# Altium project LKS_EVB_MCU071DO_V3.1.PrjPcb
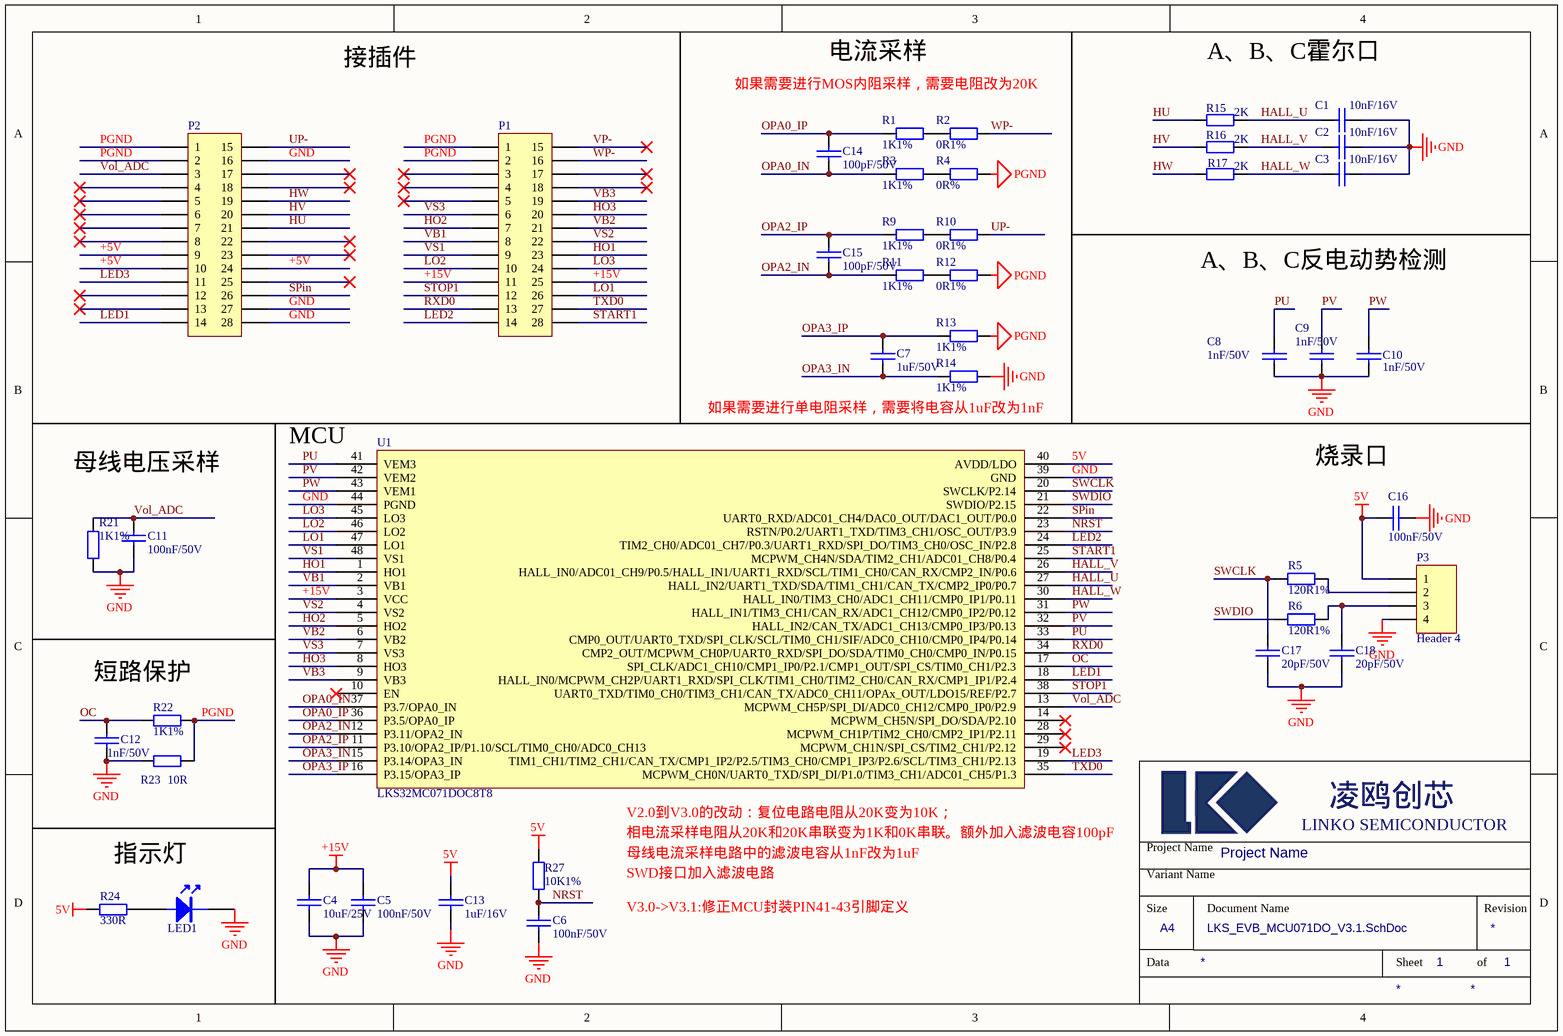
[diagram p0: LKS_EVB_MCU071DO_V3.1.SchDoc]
1 sheet, 43 parts. Net scope: global (net labels, ports and power ports of the same name join across sheets).
Board file: LKS_EVB_MCU071DO_V3.0.PcbDoc

## Sheet LKS_EVB_MCU071DO_V3.1.SchDoc
size A4; SheetNumber: 1; SheetTotal: 1; Variant Name: [No Variations]; Size: A3

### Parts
C1  10nF/16V  [0603C]
C2  10nF/16V  [0603C]
C3  10nF/16V  [0603C]
C4  10uF/25V  [0603C]
C5  100nF/50V  [0603C]
C6  100nF/50V  [0603C]
C7  1uF/50V  [0603C]
C8  1nF/50V  [0603C]
C9  1nF/50V  [0603C]
C10  1nF/50V  [0603C]
C11  100nF/50V  [0603C]
C12  1nF/50V  [0603C]
C13  1uF/16V  [0603C]
C14  100pF/50V  [0603C]
C15  100pF/50V  [0603C]
C16  100nF/50V  [0603C]
C17  20pF/50V  [0603C]
C18  20pF/50V  [0603C]
LED1  LED  [LED 0603R]  (value not drawn)
P1  Header 14X2A  [HDR 2X14 顶层]  (value not drawn)
P2  Header 14X2A  [HDR 2X14 顶层]  (value not drawn)
P3  Header 4  [HDR 1X4]
R1  1K1%  [0603R]
R2  0R1%  [0603R]
R3  1K1%  [0603R]
R4  0R%  [0603R]
R5  120R1%  [0603R]
R6  120R1%  [0603R]
R9  1K1%  [0603R]
R10  0R1%  [0603R]
R11  1K1%  [0603R]
R12  0R1%  [0603R]
R13  1K1%  [0603R]
R14  1K1%  [0603R]
R15  2K  [0603R]
R16  2K  [0603R]
R17  2K  [0603R]
R21  1K1%  [0603R]
R22  1K1%  [0603R]
R23  10R  [0603R]
R24  330R  [0603R]
R27  10K1%  [0603R]
U1  LKS32MC071DOC8T8  [TQFP48]

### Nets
5V: C13.2 C16.1 P3.1 R24.1 R27.2 U1.40(AVDD/LDO)
+15V: C4.2 C5.2 P1.11 P1.25 U1.3(VCC)
GND: C1.2 C2.2 C3.2 C4.1 C5.1 C6.2 C8.2 C9.2 C10.2 C11.1 C12.1 C13.1 C16.2 C17.1 C18.1 LED1.2(K) P2.16 P2.27 P2.28 P3.4 R14.1 R21.1 R23.2 U1.39(GND) U1.44(PGND)
PGND: P1.1 P1.2 P2.1 P2.2 R4.1 R12.1 R13.1 R22.2 R23.1
+5V: P2.9 P2.10 P2.24
HALL_U: C1.1 R15.2 U1.27(HALL_IN2/UART1_TXD/SDA/TIM1_CH1/CAN_TX/CMP2_IP0/P0.7)
HALL_V: C2.1 R16.2 U1.26(HALL_IN0/ADC01_CH9/P0.5/HALL_IN1/UART1_RXD/SCL/TIM1_CH0/CAN_RX/CMP2_IN/P0.6)
HALL_W: C3.1 R17.2 U1.30(HALL_IN0/TIM3_CH0/ADC1_CH11/CMP0_IP1/P0.11)
HO1: P1.23 U1.1(HO1)
HO2: P1.7 U1.5(HO2)
HO3: P1.20 U1.8(HO3)
HU: P2.21 R15.1
HV: P2.20 R16.1
HW: P2.19 R17.1
LED1: P2.14 U1.18(HALL_IN0/MCPWM_CH2P/UART1_RXD/SPI_CLK/TIM1_CH0/TIM2_CH0/CAN_RX/CMP1_IP1/P2.4)
LED2: P1.14 U1.24(TIM2_CH0/ADC01_CH7/P0.3/UART1_RXD/SPI_DO/TIM3_CH0/OSC_IN/P2.8)
LED3: P2.11 U1.19(TIM1_CH1/TIM2_CH1/CAN_TX/CMP1_IP2/P2.5/TIM3_CH0/CMP1_IP3/P2.6/SCL/TIM3_CH1/P2.13)
LO1: P1.26 U1.47(LO1)
LO2: P1.10 U1.46(LO2)
LO3: P1.24 U1.45(LO3)
NRST: C6.1 R27.1 U1.23(RSTN/P0.2/UART1_TXD/TIM3_CH1/OSC_OUT/P3.9)
OC: C12.2 R22.1 U1.17(SPI_CLK/ADC1_CH10/CMP1_IP0/P2.1/CMP1_OUT/SPI_CS/TIM0_CH1/P2.3)
OPA0_IN: C14.1 R3.2 U1.37(P3.7/OPA0_IN)
OPA0_IP: C14.2 R1.2 U1.36(P3.5/OPA0_IP)
OPA2_IN: C15.1 R11.2 U1.12(P3.11/OPA2_IN)
OPA2_IP: C15.2 R9.2 U1.11(P3.10/OPA2_IP/P1.10/SCL/TIM0_CH0/ADC0_CH13)
OPA3_IN: C7.2 R14.2 U1.15(P3.14/OPA3_IN)
OPA3_IP: C7.1 R13.2 U1.16(P3.15/OPA3_IP)
PU: C8.1 U1.33(CMP0_OUT/UART0_TXD/SPI_CLK/SCL/TIM0_CH1/SIF/ADC0_CH10/CMP0_IP4/P0.14) U1.41(VEM3)
PV: C9.1 U1.32(HALL_IN2/CAN_TX/ADC1_CH13/CMP0_IP3/P0.13) U1.42(VEM2)
PW: C10.1 U1.31(HALL_IN1/TIM3_CH1/CAN_RX/ADC1_CH12/CMP0_IP2/P0.12) U1.43(VEM1)
RXD0: P1.13 U1.34(CMP2_OUT/MCPWM_CH0P/UART0_RXD/SPI_DO/SDA/TIM0_CH0/CMP0_IN/P0.15)
SPin: P2.26 U1.22(UART0_RXD/ADC01_CH4/DAC0_OUT/DAC1_OUT/P0.0)
START1: P1.28 U1.25(MCPWM_CH4N/SDA/TIM2_CH1/ADC01_CH8/P0.4)
STOP1: P1.12 U1.38(UART0_TXD/TIM0_CH0/TIM3_CH1/CAN_TX/ADC0_CH11/OPAx_OUT/LDO15/REF/P2.7)
SWCLK: C17.2 R5.1 U1.20(SWCLK/P2.14)
SWDIO: R6.1 U1.21(SWDIO/P2.15)
TXD0: P1.27 U1.35(MCPWM_CH0N/UART0_TXD/SPI_DI/P1.0/TIM3_CH1/ADC01_CH5/P1.3)
UP-: P2.15 R10.1
VB1: P1.8 U1.2(VB1)
VB2: P1.21 U1.6(VB2)
VB3: P1.19 U1.9(VB3)
Vol_ADC: C11.2 P2.3 R21.2 U1.13(MCPWM_CH5P/SPI_DI/ADC0_CH12/CMP0_IP0/P2.9)
VP-: P1.15
VS1: P1.9 U1.48(VS1)
VS2: P1.22 U1.4(VS2)
VS3: P1.6 U1.7(VS3)
WP-: P1.16 R2.1
NetC18_2: C18.2 P3.3 R6.2
NetLED1_1: LED1.1(A) R24.2
NetP3_2: P3.2 R5.2
NetR1_1: R1.1 R2.2
NetR3_1: R3.1 R4.2
NetR9_1: R9.1 R10.2
NetR11_1: R11.1 R12.2

Not connected (* = marked no-connect by the designer): P1 3* 4* 5* 17* 18*; P2 4* 5* 6* 7* 8* 12* 13* 17* 18* 22* 23* 25*; U1 10(EN)* 14(MCPWM_CH5N/SPI_DO/SDA/P2.10)* 28(MCPWM_CH1P/TIM2_CH0/CMP2_IP1/P2.11)* 29(MCPWM_CH1N/SPI_CS/TIM2_CH1/P2.12)*

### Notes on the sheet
- 接插件
- 如果需要进行MOS内阻采样，需要电阻改为20K
- 如果需要进行单电阻采样，需要将电容从1uF改为1nF
- 母线电压采样
- 烧录口
- 短路保护
- (near U1) V2.0到V3.0的改动：复位电路电阻从20K变为10K；
- (near U1) 相电流采样电阻从20K和20K串联变为1K和0K串联。额外加入滤波电容100pF
- 指示灯
- 母线电流采样电路中的滤波电容从1nF改为1uF
- SWD接口加入滤波电路
- V3.0->V3.1:修正MCU封装PIN41-43引脚定义
- Labels drawn without touching a wire or pin: A、B、C反电动势检测, A、B、C霍尔口, MCU, 电流采样

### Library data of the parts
C1-C3 C8-C10 = CAP: Capacitor
C4-C7 C11-C18 = C: Capacitor
LED1 = LED: LED_Light
P1 P2 = Header 14X2A: Header, 14-Pin, Dual row
P3 = Header 4: Header, 4-Pin
R1-R6 R9-R17 R21-R24 R27 = Res: Resistor; Value: K
U1 = LKS32MC071DOC8T8: 芯片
